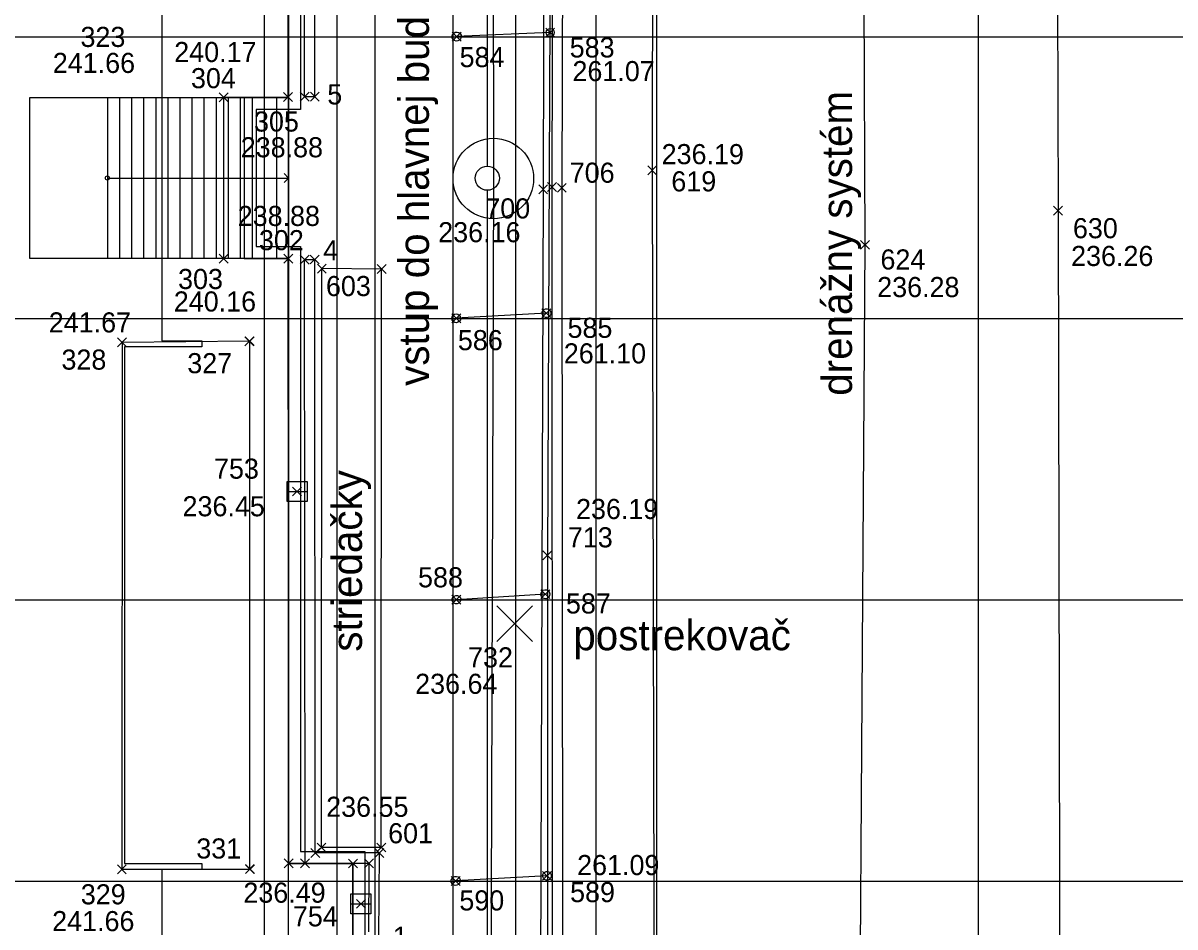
# Model space of a CAD drawing. Extents: x -264205 to -263659, y -1242401 to -1242060.
# Drawn here: x -263900.22 to -263871.58, y -1242183.01 to -1242160.53 of the extents above; entities that cross this region are included whole.
import ezdxf

# ---------------------------------------------------------------- set-up
doc = ezdxf.new("R2010")
doc.units = 0
for name, color, linetype in [('BOD_CISLO', 7, 'Continuous'), ('BOD_SYMBOL', 7, 'Continuous'), ('BOD_VYSKA', 7, 'Continuous'), ('KFA_SO_10-1_DRENAZNY_SYSTEM_IHRISKA', 7, 'Continuous'), ('KFA_SO_10-1_LIZATKA_POMOCNE', 7, 'Continuous'), ('KFA_SO_10-1_OBRUBNIKY_IHRISKO', 7, 'Continuous'), ('KFA_SO_10-1_OHREV', 7, 'Continuous'), ('KFA_SO_10-1_POSTREKOVACE', 7, 'Continuous'), ('KFA_SO_10-1_STRECHY', 7, 'Continuous'), ('KFA_SO_10-1_STRIEDACKY', 7, 'Continuous'), ('KFA_SO_10-1_TEPELNE_SENZORY_A_TRASA', 7, 'Continuous'), ('KFA_SO_10-1_TRIBUNA_A_OBVOD', 7, 'Continuous'), ('KFA_SO_10-1_VPUST_STADION_POKLOP', 7, 'Continuous'), ('KFA_SO_10-1_VSTUPY_TRIBUNA_A', 7, 'Continuous'), ('KFA_SO_40-2-II_DAZDOVA_KANALIZACIA', 7, 'Continuous'), ('OSI_STAVBY_KFA', 7, 'Continuous'), ('POPIS', 7, 'Continuous'), ('SITUACIA_DSP_2D', 7, 'Continuous')]:
    doc.layers.add(name, color=color, linetype=linetype)

msp = doc.modelspace()

# ---------------------------------------------------------------- linework, layer by layer
at = {"layer": 'BOD_SYMBOL'}
for p, q in [((-263887.22, -1242160.874), (-263887, -1242160.654)), ((-263887, -1242160.874), (-263887.22, -1242160.654)), ((-263889.546, -1242160.975), (-263889.325, -1242160.754)), ((-263889.325, -1242160.975), (-263889.546, -1242160.754)), ((-263895.337, -1242162.485), (-263895.116, -1242162.265)), ((-263895.116, -1242162.485), (-263895.337, -1242162.265)), ((-263893.737, -1242162.478), (-263893.516, -1242162.258)), ((-263893.516, -1242162.478), (-263893.737, -1242162.258)), ((-263893.324, -1242162.468), (-263893.103, -1242162.248)), ((-263893.103, -1242162.468), (-263893.324, -1242162.248)), ((-263893.072, -1242162.468), (-263892.851, -1242162.247)), ((-263892.851, -1242162.468), (-263893.072, -1242162.247)), ((-263884.686, -1242164.305), (-263884.465, -1242164.083)), ((-263884.465, -1242164.305), (-263884.686, -1242164.083)), ((-263887.395, -1242164.775), (-263887.174, -1242164.555)), ((-263887.174, -1242164.775), (-263887.395, -1242164.555)), ((-263887.177, -1242164.717), (-263886.956, -1242164.495)), ((-263886.956, -1242164.717), (-263887.177, -1242164.495)), ((-263886.932, -1242164.737), (-263886.71, -1242164.515)), ((-263886.71, -1242164.737), (-263886.932, -1242164.515)), ((-263874.595, -1242165.308), (-263874.373, -1242165.086)), ((-263874.373, -1242165.308), (-263874.595, -1242165.086)), ((-263879.395, -1242166.154), (-263879.174, -1242165.934)), ((-263879.174, -1242166.154), (-263879.395, -1242165.934)), ((-263895.337, -1242166.501), (-263895.116, -1242166.279)), ((-263895.116, -1242166.501), (-263895.337, -1242166.279)), ((-263893.732, -1242166.498), (-263893.511, -1242166.278)), ((-263893.511, -1242166.498), (-263893.732, -1242166.278)), ((-263893.326, -1242166.522), (-263893.105, -1242166.301)), ((-263893.105, -1242166.522), (-263893.326, -1242166.301)), ((-263893.074, -1242166.521), (-263892.853, -1242166.299)), ((-263892.853, -1242166.521), (-263893.074, -1242166.299)), ((-263892.898, -1242166.748), (-263892.677, -1242166.526)), ((-263892.677, -1242166.748), (-263892.898, -1242166.526)), ((-263891.41, -1242166.757), (-263891.189, -1242166.535)), ((-263891.189, -1242166.757), (-263891.41, -1242166.535)), ((-263889.557, -1242167.982), (-263889.335, -1242167.762)), ((-263889.335, -1242167.982), (-263889.557, -1242167.762)), ((-263887.316, -1242167.855), (-263887.095, -1242167.633)), ((-263887.095, -1242167.855), (-263887.316, -1242167.633)), ((-263897.866, -1242168.582), (-263897.644, -1242168.36)), ((-263897.644, -1242168.582), (-263897.866, -1242168.36)), ((-263894.698, -1242168.553), (-263894.477, -1242168.333)), ((-263894.477, -1242168.553), (-263894.698, -1242168.333)), ((-263894.692, -1242168.551), (-263894.47, -1242168.329)), ((-263894.47, -1242168.551), (-263894.692, -1242168.329)), ((-263893.514, -1242172.291), (-263893.292, -1242172.069)), ((-263893.292, -1242172.291), (-263893.514, -1242172.069)), ((-263887.291, -1242173.88), (-263887.069, -1242173.66)), ((-263887.069, -1242173.88), (-263887.291, -1242173.66)), ((-263887.34, -1242174.846), (-263887.118, -1242174.624)), ((-263887.118, -1242174.846), (-263887.34, -1242174.624)), ((-263889.552, -1242174.981), (-263889.33, -1242174.761)), ((-263889.33, -1242174.981), (-263889.552, -1242174.761)), ((-263888.104, -1242175.578), (-263887.883, -1242175.356)), ((-263887.883, -1242175.578), (-263888.104, -1242175.356)), ((-263892.905, -1242181.144), (-263892.684, -1242180.924)), ((-263892.684, -1242181.144), (-263892.905, -1242180.924)), ((-263891.419, -1242181.144), (-263891.198, -1242180.924)), ((-263891.198, -1242181.144), (-263891.419, -1242180.924)), ((-263893.062, -1242181.282), (-263892.84, -1242181.061)), ((-263892.84, -1242181.282), (-263893.062, -1242181.061)), ((-263891.467, -1242181.282), (-263891.246, -1242181.061)), ((-263891.246, -1242181.282), (-263891.467, -1242181.061)), ((-263897.87, -1242181.69), (-263897.649, -1242181.468)), ((-263897.649, -1242181.69), (-263897.87, -1242181.468)), ((-263894.688, -1242181.683), (-263894.467, -1242181.461)), ((-263894.467, -1242181.683), (-263894.688, -1242181.461)), ((-263894.687, -1242181.686), (-263894.465, -1242181.465)), ((-263894.465, -1242181.686), (-263894.687, -1242181.465)), ((-263893.721, -1242181.539), (-263893.5, -1242181.318)), ((-263893.5, -1242181.539), (-263893.721, -1242181.318)), ((-263893.315, -1242181.541), (-263893.094, -1242181.319)), ((-263893.094, -1242181.541), (-263893.315, -1242181.319)), ((-263892.125, -1242181.542), (-263891.904, -1242181.322)), ((-263891.904, -1242181.542), (-263892.125, -1242181.322)), ((-263891.724, -1242181.541), (-263891.503, -1242181.319)), ((-263891.503, -1242181.541), (-263891.724, -1242181.319)), ((-263889.568, -1242181.978), (-263889.347, -1242181.757)), ((-263889.347, -1242181.978), (-263889.568, -1242181.757)), ((-263887.299, -1242181.852), (-263887.078, -1242181.63)), ((-263887.078, -1242181.852), (-263887.299, -1242181.63)), ((-263891.927, -1242182.548), (-263891.705, -1242182.326)), ((-263891.705, -1242182.548), (-263891.927, -1242182.326))]:
    msp.add_line(p, q, dxfattribs=at)
at = {"layer": 'KFA_SO_10-1_DRENAZNY_SYSTEM_IHRISKA'}
for p, q in [((-263879.529, -1242110.498), (-263879.285, -1242166.044)), ((-263874.609, -1242111.148), (-263874.484, -1242165.197))]:
    msp.add_line(p, q, dxfattribs=at)
for points in [[(-263884.503, -1242110.771), (-263884.575, -1242164.194), (-263884.45, -1242219.174)], [(-263874.484, -1242165.197), (-263874.412, -1242198.851), (-263874.565, -1242219.834)], [(-263879.285, -1242166.044), (-263879.493, -1242197.351), (-263879.426, -1242219.321)]]:
    msp.add_lwpolyline(points, dxfattribs=at)
at = {"layer": 'KFA_SO_10-1_LIZATKA_POMOCNE'}
for p, q in [((-263887.11, -1242160.764), (-263889.436, -1242160.864)), ((-263887.205, -1242167.744), (-263889.446, -1242167.872)), ((-263887.229, -1242174.735), (-263889.441, -1242174.871)), ((-263887.188, -1242181.741), (-263889.458, -1242181.867))]:
    msp.add_line(p, q, dxfattribs=at)
for centre, major_axis, ratio in [((-263887.11, -1242160.764), (0.042, 0.0957), 0.952097), ((-263889.436, -1242160.864), (0.109, 0.033), 0.992998), ((-263889.446, -1242167.872), (0.0752, 0.0801), 0.994467), ((-263887.205, -1242167.744), (-0.021, 0.111), 0.976639), ((-263887.229, -1242174.735), (-0.013, 0.112), 0.977953), ((-263889.441, -1242174.871), (0.0918, 0.0584), 0.980965), ((-263889.458, -1242181.867), (0.091, 0.0679), 0.986033), ((-263887.188, -1242181.741), (0.023, 0.109), 0.953046)]:
    msp.add_ellipse(centre, major_axis=major_axis, ratio=ratio, dxfattribs=at)
at = {"layer": 'KFA_SO_10-1_OBRUBNIKY_IHRISKO'}
for p, q in [((-263893.214, -1242162.358), (-263893.215, -1242158)), ((-263893.214, -1242162.358), (-263892.961, -1242162.357)), ((-263893.215, -1242166.411), (-263892.964, -1242166.41)), ((-263893.204, -1242181.43), (-263893.215, -1242166.411)), ((-263892.951, -1242181.171), (-263892.964, -1242166.41)), ((-263891.356, -1242181.171), (-263892.951, -1242181.171)), ((-263891.369, -1242183.262), (-263891.356, -1242181.171)), ((-263891.613, -1242181.43), (-263893.204, -1242181.43)), ((-263891.619, -1242183.131), (-263891.613, -1242181.43))]:
    msp.add_line(p, q, dxfattribs=at)
msp.add_lwpolyline([(-263892.961, -1242162.357), (-263892.972, -1242157.989), (-263892.952, -1242147.616), (-263891.347, -1242147.614), (-263891.367, -1242145.649)], dxfattribs=at)
at = {"layer": 'KFA_SO_10-1_OHREV'}
for points in [[(-263887.153, -1242108.434), (-263887.285, -1242164.665), (-263887.476, -1242220.33)], [(-263886.925, -1242108.434), (-263887.067, -1242164.606), (-263887.048, -1242220.33)], [(-263886.653, -1242108.434), (-263886.821, -1242164.626), (-263886.77, -1242220.33)]]:
    msp.add_lwpolyline(points, dxfattribs=at)
at = {"layer": 'KFA_SO_10-1_POSTREKOVACE'}
for p, q in [((-263888.435, -1242175.909), (-263887.551, -1242175.025)), ((-263887.551, -1242175.909), (-263888.435, -1242175.025))]:
    msp.add_line(p, q, dxfattribs=at)
at = {"layer": 'KFA_SO_10-1_STRECHY'}
msp.add_line((-263889.533, -1242219.411), (-263889.511, -1242109.378), dxfattribs=at)
at = {"layer": 'KFA_SO_10-1_STRIEDACKY'}
msp.add_line((-263891.308, -1242181.034), (-263892.795, -1242181.034), dxfattribs=at)
for points in [[(-263892.795, -1242181.034), (-263892.787, -1242166.637)], [(-263891.308, -1242181.034), (-263891.3, -1242166.646), (-263892.787, -1242166.637)]]:
    msp.add_lwpolyline(points, dxfattribs=at)
at = {"layer": 'KFA_SO_10-1_TEPELNE_SENZORY_A_TRASA'}
msp.add_lwpolyline([(-263827.921, -1242121.921), (-263875.963, -1242121.979), (-263885.626, -1242121.792), (-263887.003, -1242121.689), (-263887.052, -1242145.021), (-263887.18, -1242173.77), (-263887.177, -1242203.116), (-263886.892, -1242206.901)], dxfattribs=at)
at = {"layer": 'KFA_SO_10-1_TRIBUNA_A_OBVOD'}
msp.add_lwpolyline([(-263892.039, -1242220.661), (-263892.154, -1242220.367), (-263892.023, -1242220.311), (-263892.026, -1242218.259), (-263892.022, -1242218.258), (-263892.014, -1242181.432), (-263893.611, -1242181.428), (-263893.622, -1242166.388), (-263895.226, -1242166.39), (-263895.226, -1242162.375), (-263893.627, -1242162.368), (-263893.627, -1242147.332), (-263892.023, -1242147.335), (-263892.008, -1242110.521), (-263892.009, -1242110.521), (-263892.017, -1242108.459), (-263892.149, -1242108.408), (-263892.034, -1242108.1)], dxfattribs=at)
at = {"layer": 'KFA_SO_10-1_VPUST_STADION_POKLOP'}
for p, q in [((-263893.403, -1242172.18), (-263893.403, -1242172.18)), ((-263891.816, -1242182.437), (-263891.816, -1242182.437))]:
    msp.add_line(p, q, dxfattribs=at)
for points in [[(-263893.653, -1242172.18), (-263893.653, -1242171.93), (-263893.153, -1242171.93), (-263893.153, -1242172.43), (-263893.653, -1242172.43), (-263893.653, -1242172.18), (-263893.153, -1242172.18)], [(-263892.066, -1242182.437), (-263892.066, -1242182.187), (-263891.566, -1242182.187), (-263891.566, -1242182.687), (-263892.066, -1242182.687), (-263892.066, -1242182.437), (-263891.566, -1242182.437)]]:
    msp.add_lwpolyline(points, dxfattribs=at)
at = {"layer": 'KFA_SO_10-1_VSTUPY_TRIBUNA_A'}
msp.add_line((-263894.578, -1242181.572), (-263894.581, -1242168.44), dxfattribs=at)
msp.add_lwpolyline([(-263894.581, -1242168.44), (-263894.588, -1242168.443), (-263897.755, -1242168.471), (-263897.759, -1242181.579), (-263894.576, -1242181.575), (-263894.578, -1242181.572)], dxfattribs=at)
at = {"layer": 'KFA_SO_40-2-II_DAZDOVA_KANALIZACIA'}
msp.add_lwpolyline([(-263814.907, -1242107.856), (-263851.887, -1242107.945), (-263888.606, -1242107.773), (-263888.523, -1242164.395), (-263888.701, -1242220.786)], dxfattribs=at)
msp.add_circle((-263888.523, -1242164.395), 1, dxfattribs=at)
at = {"layer": 'OSI_STAVBY_KFA'}
for p, q in [((-263894.218, -1242083.237), (-263894.218, -1242246.707)), ((-263892.418, -1242083.237), (-263892.418, -1242246.707)), ((-263891.468, -1242083.237), (-263891.468, -1242246.707)), ((-263884.468, -1242083.237), (-263884.468, -1242246.707)), ((-263876.468, -1242083.237), (-263876.468, -1242246.707)), ((-263792.653, -1242160.882), (-263909.343, -1242160.882)), ((-263792.653, -1242167.882), (-263909.343, -1242167.882)), ((-263792.653, -1242174.882), (-263909.343, -1242174.882)), ((-263792.653, -1242181.882), (-263909.343, -1242181.882))]:
    msp.add_line(p, q, dxfattribs=at)
at = {"layer": 'SITUACIA_DSP_2D'}
for p, q in [((-263888.673, -1242108.177), (-263888.673, -1242164.087)), ((-263887.968, -1242220.33), (-263887.968, -1242108.434)), ((-263885.968, -1242216.882), (-263885.968, -1242111.882)), ((-263893.618, -1242162.382), (-263893.618, -1242118.282)), ((-263893.618, -1242181.432), (-263893.618, -1242147.332)), ((-263893.618, -1242147.332), (-263893.618, -1242162.382)), ((-263893.318, -1242147.632), (-263893.318, -1242162.682)), ((-263896.768, -1242160.332), (-263896.768, -1242168.432)), ((-263900.043, -1242166.382), (-263900.043, -1242162.382)), ((-263900.043, -1242162.382), (-263893.618, -1242162.382)), ((-263898.118, -1242162.382), (-263898.118, -1242166.382)), ((-263897.818, -1242162.382), (-263897.818, -1242166.382)), ((-263897.518, -1242162.382), (-263897.518, -1242166.382)), ((-263897.218, -1242162.382), (-263897.218, -1242166.382)), ((-263896.918, -1242162.382), (-263896.918, -1242166.382)), ((-263896.618, -1242162.382), (-263896.618, -1242166.382)), ((-263896.318, -1242162.382), (-263896.318, -1242166.382)), ((-263896.018, -1242162.382), (-263896.018, -1242166.382)), ((-263895.718, -1242162.382), (-263895.718, -1242166.382)), ((-263895.418, -1242162.382), (-263895.418, -1242166.382)), ((-263895.118, -1242162.382), (-263895.118, -1242166.382)), ((-263894.818, -1242162.382), (-263894.818, -1242166.382)), ((-263893.618, -1242162.382), (-263894.718, -1242162.382)), ((-263894.718, -1242162.382), (-263894.718, -1242166.382)), ((-263894.518, -1242162.382), (-263894.518, -1242166.382)), ((-263894.218, -1242162.382), (-263894.218, -1242166.382)), ((-263893.918, -1242162.382), (-263893.918, -1242166.382)), ((-263893.618, -1242162.382), (-263893.618, -1242166.382)), ((-263893.318, -1242162.682), (-263894.418, -1242162.682)), ((-263894.418, -1242162.682), (-263894.418, -1242166.082)), ((-263898.118, -1242164.382), (-263893.618, -1242164.382)), ((-263893.618, -1242164.382), (-263893.721, -1242164.274)), ((-263893.618, -1242164.382), (-263893.721, -1242164.491)), ((-263888.673, -1242164.687), (-263888.673, -1242220.396)), ((-263894.418, -1242166.082), (-263893.318, -1242166.082)), ((-263893.318, -1242166.082), (-263893.318, -1242181.132)), ((-263893.618, -1242166.382), (-263900.043, -1242166.382)), ((-263894.718, -1242166.382), (-263893.618, -1242166.382)), ((-263893.618, -1242210.482), (-263893.618, -1242166.382)), ((-263893.618, -1242166.382), (-263893.618, -1242181.432)), ((-263895.768, -1242168.582), (-263897.693, -1242168.582)), ((-263897.693, -1242168.582), (-263897.693, -1242181.432)), ((-263896.768, -1242168.432), (-263895.768, -1242168.432)), ((-263895.768, -1242168.432), (-263895.768, -1242168.582)), ((-263893.318, -1242181.132), (-263891.718, -1242181.132)), ((-263891.718, -1242181.132), (-263891.718, -1242220.206)), ((-263897.693, -1242181.432), (-263895.768, -1242181.432)), ((-263895.768, -1242181.582), (-263896.768, -1242181.582)), ((-263896.768, -1242181.582), (-263896.768, -1242203.332)), ((-263895.768, -1242181.432), (-263895.768, -1242181.582)), ((-263892.018, -1242181.432), (-263893.618, -1242181.432)), ((-263893.618, -1242181.432), (-263892.018, -1242181.432)), ((-263892.018, -1242220.33), (-263892.018, -1242181.432)), ((-263892.018, -1242181.432), (-263892.018, -1242220.33))]:
    msp.add_line(p, q, dxfattribs=at)
for centre, radius in [((-263888.673, -1242164.387), 0.3), ((-263898.118, -1242164.382), 0.05)]:
    msp.add_circle(centre, radius, dxfattribs=at)

# ---------------------------------------------------------------- texts
at = {"layer": 'BOD_CISLO'}
for s, p in [('323', (-263898.787, -1242161.122)), ('583', (-263886.625, -1242161.384)), ('584', (-263889.362, -1242161.624)), ('304', (-263896.04, -1242162.148)), ('5', (-263892.651, -1242162.551)), ('305', (-263894.473, -1242163.227)), ('706', (-263886.624, -1242164.5)), ('619', (-263884.098, -1242164.715)), ('700', (-263888.723, -1242165.388)), ('630', (-263874.114, -1242165.881)), ('302', (-263894.35, -1242166.178)), ('4', (-263892.753, -1242166.43)), ('624', (-263878.899, -1242166.658)), ('303', (-263896.361, -1242167.144)), ('603', (-263892.684, -1242167.319)), ('585', (-263886.679, -1242168.358)), ('586', (-263889.405, -1242168.665)), ('328', (-263899.26, -1242169.149)), ('327', (-263896.132, -1242169.238)), ('753', (-263895.467, -1242171.862)), ('713', (-263886.67, -1242173.57)), ('588', (-263890.395, -1242174.565)), ('587', (-263886.719, -1242175.215)), ('732', (-263889.152, -1242176.556)), ('601', (-263891.139, -1242180.931)), ('331', (-263895.908, -1242181.31)), ('329', (-263898.779, -1242182.45)), ('590', (-263889.368, -1242182.602)), ('589', (-263886.615, -1242182.395)), ('754', (-263893.507, -1242182.998)), ('1', (-263891.02, -1242183.503))]:
    msp.add_text(s, height=0.5, dxfattribs=at).set_placement(p)
at = {"layer": 'BOD_VYSKA'}
for s, p in [('240.17', (-263896.456, -1242161.498)), ('241.66', (-263899.475, -1242161.769)), ('261.07', (-263886.556, -1242161.973)), ('238.88', (-263894.803, -1242163.867)), ('236.19', (-263884.339, -1242164.038)), ('238.88', (-263894.878, -1242165.575)), ('236.16', (-263889.894, -1242165.98)), ('236.26', (-263874.159, -1242166.571)), ('236.28', (-263878.98, -1242167.344)), ('240.16', (-263896.467, -1242167.703)), ('241.67', (-263899.575, -1242168.224)), ('261.10', (-263886.771, -1242168.994)), ('236.45', (-263896.25, -1242172.797)), ('236.19', (-263886.467, -1242172.865)), ('236.64', (-263890.467, -1242177.214)), ('236.55', (-263892.679, -1242180.273)), ('261.09', (-263886.44, -1242181.722)), ('236.49', (-263894.737, -1242182.409)), ('241.66', (-263899.491, -1242183.117))]:
    msp.add_text(s, height=0.5, dxfattribs=at).set_placement(p)
at = {"layer": 'POPIS'}
for s, p in [('vstup do hlavnej budovy', (-263890.125, -1242169.552)), ('drenážny systém', (-263879.607, -1242169.798)), ('striedačky', (-263891.789, -1242176.165))]:
    msp.add_text(s, height=0.75, rotation=90, dxfattribs=at).set_placement(p)
msp.add_text('postrekovač', height=0.75, dxfattribs=at).set_placement((-263886.534, -1242176.129))

doc.saveas('drawing.dxf')
